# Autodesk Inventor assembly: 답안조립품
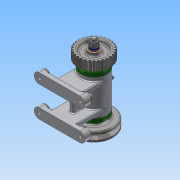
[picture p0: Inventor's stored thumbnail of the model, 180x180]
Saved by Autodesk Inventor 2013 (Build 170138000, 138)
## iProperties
Created: 2015-11
Part Number: 답안조립품
Document SubType Name: Assembly
Designer: Administrator
Author: Administrator
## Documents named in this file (16)
- C:\Users\Administrator\Desktop\451110V1050\답안조립품.iam
- C:\Users\Administrator\Desktop\451110V1050\본체.ipt
- C:\Users\Administrator\Desktop\451110V1050\V벨트풀리.ipt
- C:\Users\Administrator\Desktop\451110V1050\너트 M 8.ipt
- C:\Users\Administrator\Desktop\451110V1050\니플 M 6 x 0.75.ipt
- C:\Users\Administrator\Desktop\451110V1050\베어링 15 x 32 x 9.ipt
- C:\Users\Administrator\Desktop\451110V1050\볼트 M 6 x 8.ipt
- C:\Users\Administrator\Desktop\451110V1050\볼트 M4 x 12.ipt
- C:\Users\Administrator\Desktop\451110V1050\스퍼기어.ipt
- C:\Users\Administrator\Desktop\451110V1050\스프링와셔 8.ipt
- C:\Users\Administrator\Desktop\451110V1050\오일 실 15 25 7.ipt
- C:\Users\Administrator\Desktop\451110V1050\와셔 6x11.5.ipt
- C:\Users\Administrator\Desktop\451110V1050\와셔 8x17.ipt
- C:\Users\Administrator\Desktop\451110V1050\축.ipt
- C:\Users\Administrator\Desktop\451110V1050\커버.ipt
- C:\Users\Administrator\Desktop\451110V1050\키 3 x 3 x 12.ipt
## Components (11 placed, 3 different names)
1. V벨트풀리:1
2. KS B 2023 6002 - 15 x 32 x 9:1
3. KS B 2023 6002 - 15 x 32 x 9:2
4. ISO 4762 M4 x 12:2
5. ISO 4762 M4 x 12:1
6. ISO 4762 M4 x 12:3
7. ISO 4762 M4 x 12:4
8. ISO 4762 M4 x 12:5
9. ISO 4762 M4 x 12:6
10. ISO 4762 M4 x 12:7
11. ISO 4762 M4 x 12:8
